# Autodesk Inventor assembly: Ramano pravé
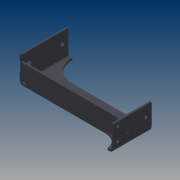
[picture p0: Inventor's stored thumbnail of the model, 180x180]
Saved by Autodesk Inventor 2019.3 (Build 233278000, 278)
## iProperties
Created: 2019-02
Part Number: Ramano pravé
Material: Všeobecné
Document SubType Name: Assembly
Designer: B-hon
Author: B-hon
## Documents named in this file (3)
- C:\Users\B-hon\OneDrive\Plocha\Bakalářka22\Deska dolní\Ramano pravé.iam
- C:\Users\B-hon\OneDrive\Plocha\Bakalářka22\Deska dolní\Rameno pravé.ipt
- C:\Users\B-hon\OneDrive\Plocha\Bakalářka22\Deska dolní\Výztuha ramene p.ipt
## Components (2 placed, 2 different names)
1. Rameno pravé:1 — Proti sobě:1, Stejný směr:1, Stejný směr:2
2. Výztuha ramene p:1 — Proti sobě:1, Stejný směr:1, Stejný směr:2
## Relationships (3: Flush 2, Mate 1)
- Proti sobě:1 [Mate]: Rameno pravé:1 ↔ Výztuha ramene p:1
- Stejný směr:1 [Flush]: Rameno pravé:1 ↔ Výztuha ramene p:1
- Stejný směr:2 [Flush]: Rameno pravé:1 ↔ Výztuha ramene p:1
